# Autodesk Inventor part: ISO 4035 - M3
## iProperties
Created: 2004-09
Part Number: ISO 4035 - M3
Material: Standard
Catalog Web Link: file:///C:/Programme/Autodesk/Inventor 5.3/Content/Din/index.htm?doNavigateId=CDA43926-C454-11D4-A9F1-0080AD303E0A|5F32A077B0DC11D4BA6900C04F798F98|true
Description: Sechskantmutter
Document SubType Name: Standard Catalog Part
Standard: ISO 4035 - M3
Designer: Ulrich
Control State: 0
Master: False
Checked Out: False
Shininess: 20.0
Angle Display Precision: 2
Document Length Units: 11269
Document Angle Units: 11279
Document Time Units: 11290
Document Mass Units: 11283
Document Length Units Precision: 3
Document Angle Units Precision: 2
Compacted: True
KLASSIFIKATION: 31161727 un/spsc
HERSTELLER: DIN Normsystem
Density: 0.0
Volumn: 0.0
Area: 0.0
PropertySet Name: Model Information
Author: Ulrich
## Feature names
1. Basis1
